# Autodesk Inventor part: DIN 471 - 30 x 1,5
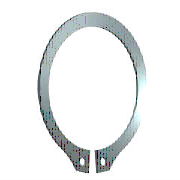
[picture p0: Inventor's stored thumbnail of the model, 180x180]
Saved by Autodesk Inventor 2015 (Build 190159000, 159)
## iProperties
IsCustomPart: 0
Created: 2011-02
Part Number: DIN 471 - 30 x 1,5
Material: Steel, Mild
Description: Rugós rögzítőgyűrű
Document SubType Name: Modeling
Standard: DIN 471
Designer: Marci
Standards Organization: DIN
Language: hu-HU
Size Designation: 30 x 1,5
Categories: <MemberInstance><Categories><Category DisplayName="Tengelyalkatrészek" InternalName="7f7aeb1f-a693-4053-b835-cee3144e0d98" Mnemonic="SHFT"><Category DisplayName
Density: 1 g/cm^3
Appearance: Steel
Author: Marci
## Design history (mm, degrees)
sketch "Vázlat1"
  geometry: L1 (-6, 0)-(6, 0) reference; L2 (0, 20.189)-(0, -80.536) reference; L3 (-48.09, 0)-(48.09, 0) reference; L4 (-0.5, -29.291)-(-0.5, -34.291); L5 (-0.5, -6.54)-(-0.5, -13.29); L6 (-2.795, 3.5)-(3.672, 3.5); L7 (0.5, -6.54)-(0.5, -13.29); L8 (0.5, -29.291)-(0.5, -34.291); C1 r 1 at (-2, -32.182); C2 r 1 at (2, -32.182); A1 r 14.3 centre (0, -15) between (0.5, -29.291) and (-0.5, -29.291); A2 r 17.625 centre (0, -14.125) between (5.341, -30.921) and (-5.341, -30.921); A3 r 19.298 centre (0, -15) between (-2.231, -34.168) and (-0.5, -34.291); A4 r 2 centre (-2, -32.182) between (-3.974, -32.504) and (-2.231, -34.168); A5 r 2 centre (-5.948, -32.827) between (-3.974, -32.504) and (-5.341, -30.921); A6 r 2 centre (5.948, -32.827) between (5.341, -30.921) and (3.974, -32.504); A7 r 2 centre (2, -32.182) between (2.231, -34.168) and (3.974, -32.504); A8 r 19.298 centre (0, -15) between (0.5, -34.291) and (2.231, -34.168)
  constraints: 16 point on circle, 12 end point, 10 centre point, 9 symmetric about line, 5 point on line, 4 tangent, 3 coincident, 2 horizontal, 1 perpendicular, 1 vertical, 5 other
  dimensions: "d0" = 28.6 diameter of A1 (= ND); "d1" = 5 distance of L4.end L4.start (= SRB2); "d6" = 0.5 distance between parallel lines of L2 L5 (= 0.25 x SD5); "d7" = 3.5 distance between parallel lines of L6 L3 (= SRB1); "d8" = 0.875 distance of A1.centre A2.centre (= 0.25 x SRB1); "d9" = 2 radius of A4 (= SD5); "d10" = 2 radius of A5 (= SD5); "d11" = 1.5 distance from line of L4 A4.centre (= 0.75 x SD5); "d12" = 2 diameter of C1 (= SD5); "d13" = 2 diameter of C2 (= SD5); "d14" = 15 distance from line of A1.centre L1 (= 0.5 x WD)
extrude "Test" new body sketch "Vázlat1" distance "d2" = 1.5 (= SD); taper "d3" = 0 deg
workaxis "Work Axis1"
workplane "Work Plane1"
body "Solid1"
other parameters: "SD" = 1.5 [user parameter; used in 1 equation term], "SRB1" = 3.5 [user parameter; used in 2 equation terms], "ND" = 28.6 [user parameter; used in 1 equation term], "SRB2" = 5 [user parameter; used in 1 equation term], "SD5" = 2 [user parameter; used in 6 equation terms], "d15" = 0, "d16" = 0, "d17" = 0, "d41" = 0, "d42" = 0, "SD3" = 27.9 [user parameter], "WDMAX" = 32 [user parameter]
